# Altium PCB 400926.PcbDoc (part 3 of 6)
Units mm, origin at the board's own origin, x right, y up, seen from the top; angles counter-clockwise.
Board outline 148.5 x 63.5 mm, 4 copper layers (Top Layer, Mid-Layer 1, Mid-Layer 2, Bottom Layer), stack 1.514 mm thick; 311 components, 281 nets, 1495 pads, 2232 vias.
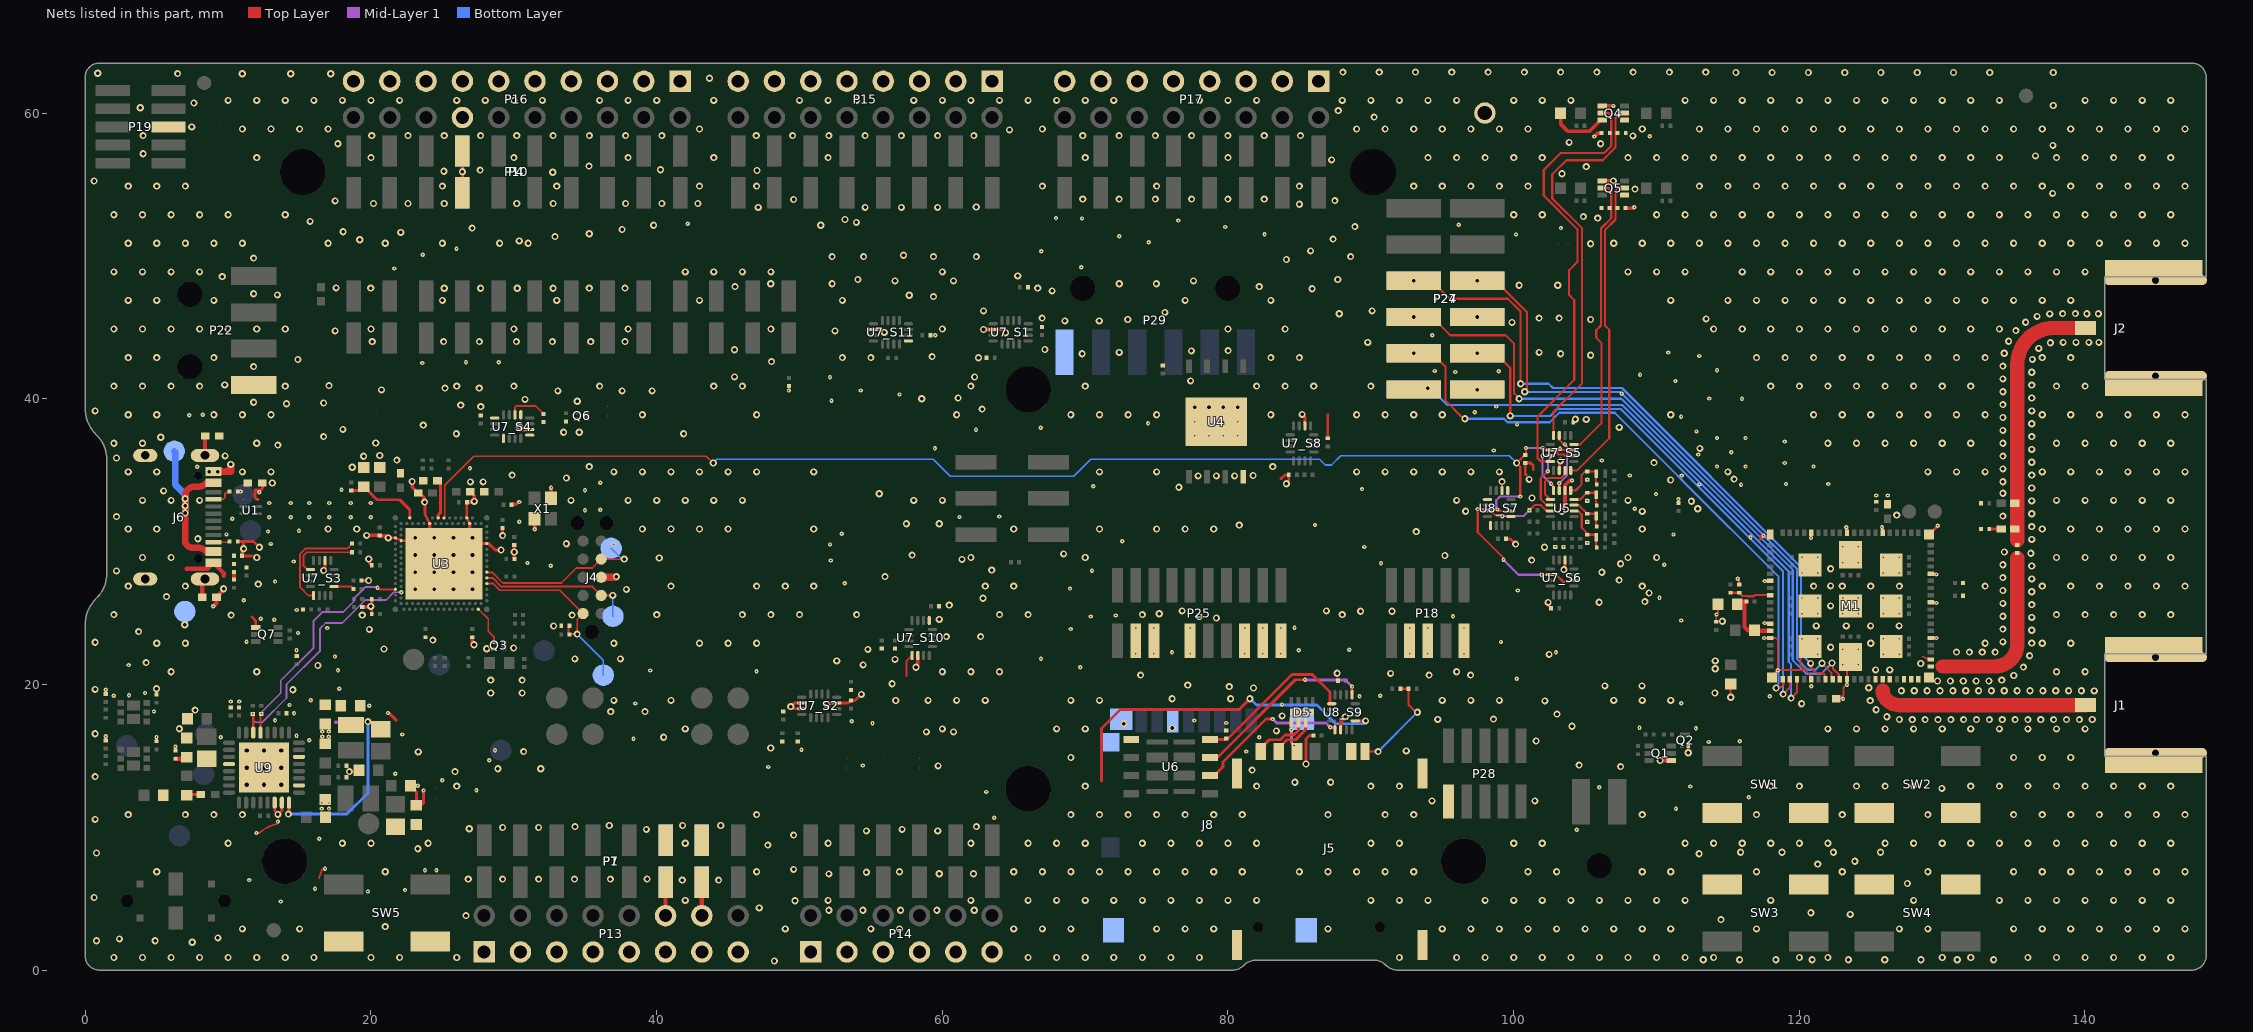
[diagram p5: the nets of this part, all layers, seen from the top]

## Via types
v1: diameter 0.5, hole 0.25, Top Layer to Bottom Layer, tented both sides, 1704 vias
v2: diameter 0.3, hole 0.1, Top Layer to Mid-Layer 1, tented top, 426 vias
v3: diameter 0.3, hole 0.1, Top Layer to Mid-Layer 1, tented both sides, 93 vias
v4: diameter 0.61, hole 0.305, Top Layer to Bottom Layer, tented both sides, 9 vias

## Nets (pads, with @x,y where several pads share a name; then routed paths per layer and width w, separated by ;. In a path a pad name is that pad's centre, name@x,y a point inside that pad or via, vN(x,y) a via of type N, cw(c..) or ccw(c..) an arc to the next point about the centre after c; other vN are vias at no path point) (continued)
GND: C1.2 C2.2 C3.2 C4.2 C5.2 C6.2 C7.2 C8.1 C9.1 C10.2 C11.1 C19.1 C24.1 C25.1 C26.2 C27.1 C28.2 C29.1 C30.2 C31.1 C32.1 C33.1 C34.2 C35.1 C36.1 C37.2 C38.2 C39.2 C40.1 C41.1 C42.1 C43.1 C44.2 C45.1 C46.1 C47.1 C48.2 C49.1 C50.1 C51.1 C52_S1.2 C52_S2.2 C52_S3.2 C52_S4.2 C52_S5.2 C52_S6.2 C52_S8.2 C52_S10.2 C52_S11.2 C53_S7.2 C53_S9.2 C54.1 C55.1 C56.1 C57.1 C58.1 C59.1 C60.1 C61.2 C62.2 C63.2 C64.1 C65.1 C66.1 C67.1 C68.1 C69.1 C70.1 C71.1 C72.1 D5.9 J1.2 J2.2 J4.3 J5.0 J5.C5 J6.A1 J6.A12 J8.0 J8.6 J8.9 M1.1 M1.7 M1.13 M1.15 M1.20 M1.25 M1.30 M1.34 M1.36 M1.38 M1.39 M1.40 M1.41 M1.43 M1.46 M1.51 M1.55 M1.60 M1.66 M1.71 M1.76 M1.105 M1.106 M1.107 M1.108 M1.109 M1.110 M1.111 M1.112 M1.113 P1.6 P1.7 P4.7 P7.6 P7.7 P10.7 P13.1 P13.3 P13.5 P13.7 P13.9 P13.11 P13.12 P13.13 P13.14 P13.15 P14.1 P14.3 P14.5 P14.7 P14.9 P14.11 P15.1 P15.3 P15.5 P15.7 P15.9 P15.11 P15.13 P15.15 P16.1 P16.3 P16.5 P16.7 P16.9 P16.11 P16.13 P16.14 P16.15 P16.17 P16.19 P17.1 P17.3 P17.5 P17.7 P17.9 P17.11 P17.13 P17.15 P18.3 P18.5 P18.9 P19.5 P22.4 P24.8 P24.12 P25.3 P25.5 P25.9 P25.15 P25.17 P25.19 P27.8 P27.12 P28.1 P29.1 Q1.1 Q2.2 Q3.2 Q4.1 Q4.4 Q5.1 Q5.4 Q6.2 Q7.1 R3.1 R7.1 R13.2 R14.1 R17.2 R18.1 R24.1 R31.2 R32.1 R36.2 R37.2 R38.1 R43.1 R44.1 R45.1 R46.1 R47.1 R59.1 R65.1 R67.2 R68.1 R70.1 R71.1 R72.2 R73.1 R74.1 R76.2 R78.1 R80.2 R81.2 R85.2 R86.2 SB19.1 SW1.1 SW2.1 SW3.1 SW4.1 SW5.1 TP18.1 TP24.1 U1.5 U1.8 U3.104 U3.A25 U3.B12 U3.B26 U3.G1 U3.H2 U3.J31 U4.4 U4.9 U5.6 U6.1 U7_S1.6 U7_S2.6 U7_S2.7 U7_S2.15 U7_S3.6 U7_S4.6 U7_S5.6 U7_S6.6 U7_S8.6 U7_S10.6 U7_S11.6 U8_S7.6 U8_S9.6 U9.2 U9.6 U9.30 U9.31 U9.33 X1.2 X1.4 | length 105
  Top Layer w0.125: v2(12,9.599) 12.14,9.599 ccw(c12.14,9.724) 12.221,9.629 cw(c13.97,7.62) 13.4,10.222 ccw(c13.373,10.344) 13.497,10.333 ccw(c12.7,10.399) v2(13.5,10.399) ; 16.4,6.399 16.4,6.503 cw(c16.525,6.502) 16.41,6.552 ccw(c13.97,7.62) 16.555,6.975 cw(c16.676,6.944) 16.618,7.055 cw(c16.8,6.699) v2(16.8,7.099) ; C1.2@114.19,24.384 114.204,24.398 114.204,24.882 v3(114.219,24.897) 114.219,24.944 114.325,25.05 C7.2@114.325,25.599 ; C3.2@115.2,19.949 115.2,19.111 v1(115.212,19.099) ; v3(115.705,27.399) 115.705,27.351 115.8,27.256 C10.2@115.8,26.984 ; 117.2,30.099 117.3,30.199 117.3,30.399 v3(117.5,30.399) 117.875,30.399 M1.1@117.975,30.499 ; v2(117.55,23.249) M1.15@117.975,23.249 118.35,23.249 118.5,23.099 v3(118.5,20.999) 120.43,20.999 ; M1.107@120.75,22.649 120.65,22.649 120.1,22.099 120.1,21.329 120.43,20.999 ; M1.25@120.85,20.374 120.763,20.461 120.763,20.667 120.43,20.999 ; C6.2@122.85,18.999 123.114,19.263 123.114,19.813 123.336,20.035 123.336,20.36 M1.30@123.35,20.374 123.35,21.674 M1.108@123.6,21.924 ; 128.642,21.944 128.744,21.944 128.87,21.817 129.157,21.817 M1.43@129.225,21.749
  Top Layer w0.15: P4.7@26.416,54.415 P4.7@26.416,57.345 ; U8_S7.6@99.2,33.574 v1(99.2,34.199)
  Top Layer w0.165: U3.A25@26.725,31.658 U3.B26@26.925,31.258
  Top Layer w0.187: v1(21.225,30.258) U3.G1@21.725,30.258 U3.G1@21.725,30.258 cw(c21.634,30.094) U3.G1@21.766,30.227 ; U3.G1@21.766,30.227 21.775,30.219 ccw(c21.907,30.351) 21.907,30.164 21.957,30.164 cw(c21.956,29.977) U3.H2@22.125,30.058 U3.104@22.825,30.058 ; v1@23.8,32.862 23.8,31.971 23.8,31.928 23.819,31.889 U3.B12@24.125,31.258
  Top Layer w0.2: R80.2@1.45,16.084 v2(1.448,16.367) ; R76.2@1.45,19.334 v2(1.448,19.617) ; R81.2@5,16.019 v2@5,16.302 ; v2(6.325,15.649) v2(6.325,15.649) C67.1@6.327,15.366 ; C54.1@7.127,12.246 7.18,12.299 C64.1@8.1,12.299 ; R70.1@10.685,29.999 11.1,29.999 ; R71.1@10.685,33.499 R71.1@10.714,33.528 ; v1@10.985,29.499 C8.1@10.985,28.999 11.65,28.999 ; v1(11.1,29.499) 11.1,29.999 ; 11.68,24.719 11.95,24.449 11.95,24.074 Q7.1@11.95,23.999 ; U1.8@12.1,32.949 cw(c12.1,33.149) 11.9,33.149 11.9,33.599 12.2,33.599 ccw(c12.2,33.824) 12.425,33.824 12.425,34.074 ccw(c12.4,34.074) C9.1@12.4,34.099 ; v1(12.2,29.599) 11.8,29.999 11.1,29.999 ; U9.30@13.275,11.724 13.275,11.166 13.5,10.941 v1(13.5,10.899) 13.775,11.174 U9.31@13.775,11.724 ; v1(16.7,27.974) 16.8,28.074 U7_S3.6@16.8,28.674 ; R24.1@19.36,27.274 v1(19.85,27.274) ; R65.1@19.4,25.414 v1@19.956,25.414 ; v1(20,25.458) 20.065,25.393 R31.2@20.065,24.924 ; v1@20.065,25.523 C26.2@20.065,25.958 ; v2(21.2,17.999) 21.219,17.98 21.294,17.98 21.787,17.486 ; C69.1@22.777,12.896 22.777,12.871 23.052,12.596 23.076,12.596 23.194,12.479 C70.1@23.194,11.548 23.245,11.599 23.583,11.599 23.7,11.716 v2@23.7,12.599 ; U3.A25@26.725,31.658 C39.2@26.725,32.754 ; v1@28.075,22.499 v1(28.125,22.499) Q3.2@28.625,22.499 ; U7_S2.7@50.175,18.299 49.55,18.299 v1(49.4,18.449) 49.65,18.699 U7_S2.6@50.175,18.699 ; v1(51.925,18.599) 52.025,18.699 U7_S2.15@52.625,18.699 53.44,18.699 C52_S2.2@53.6,18.859 ; C52_S2.2@53.625,18.884 53.91,18.884 54.15,19.124 ; U7_S11.6@55.193,44.849 55.748,44.849 v1(55.948,44.649) ; 83.725,34.399 83.996,34.67 C52_S8.2@84.268,34.67 84.268,34.217 v1(84.1,34.049) ; v1(85.2,38.899) 85.4,38.699 U7_S8.6@85.4,38.099 ; v1(85.475,14.429) 85.475,16.174 85.725,16.424 C48.2@85.99,16.424 ; 87,38.882 87.003,38.88 R38.1@87.003,37.23 ; C53_S7.2@99.482,30.191 99.783,30.191 v1(100.15,29.824) ; 100.9,34.649 100.825,34.724 R47.1@100.825,35.489 101.236,35.489 101.388,35.337 101.388,35.037 ; v1(102.429,25.743) 102.486,25.685 102.486,25.5 102.638,25.348 C52_S6.2@102.638,25.333 ; U7_S5.6@103.21,34.983 103.21,35.574 v1(103.285,35.649) ; v1(103.535,28.042) 103.61,28.117 U7_S6.6@103.61,28.708 ; R46.1@106.16,53.349 R46.1@106.195,53.314 ; v1(112.24,15.22) Q2.2@112.24,15.749 ; v3(117.588,27.236) 117.595,27.242 117.968,27.242 M1.7@117.975,27.249 ; v3(117.6,24.299) 117.619,24.28 117.944,24.28 M1.13@117.975,24.249 ; M1.20@118.1,20.499 118.35,20.749 118.35,20.832 118.5,20.982 v3(118.5,20.999) ; v3(120.838,30.248) 120.844,30.254 120.844,30.618 M1.76@120.85,30.624 ; v3(123.3,30.999) 123.35,30.949 M1.71@123.35,30.624 ; v3(125.8,30.999) 125.85,30.949 M1.66@125.85,30.624 ; M1.60@129.1,30.499 v3(129.7,31.099) ; M1.46@129.225,23.249 v3(129.605,23.248) ; M1.51@129.225,25.749 129.256,25.718 129.581,25.718 v3(129.6,25.699) ; M1.55@129.225,27.749 129.55,27.749 v3(129.6,27.699)
  Top Layer w0.225: v1(19.864,28.778) 19.917,28.725 19.917,28.496 20.065,28.348 C25.1@20.065,28.333 ; U3.104@24.125,29.858 U3.B12@24.125,31.258 ; U3.B26@26.925,31.258 26.925,29.858 U3.J31@28.125,29.858 28.275,29.858 28.725,29.408 v1(29.125,29.408) ; v1@29.225,30.425 C33.1@29.225,30.948 ; C34.2@29.86,32.574 29.86,32.588 29.882,32.611 30.176,32.611 30.331,32.765 v2(30.405,32.765) ; C30.2@30.05,29.748 v1(30.05,29.27) 30.05,28.793 C32.1@30.06,28.783
  Top Layer w0.25: C51.1@10.425,27.334 C50.1@10.425,27.864 ; v1(19.708,30.433) 19.713,30.428 20.6,30.428 C24.1@20.6,30.433 ; C24.1@20.625,30.423 20.65,30.413 20.995,30.413 cw(c20.994,30.163) v1(21.225,30.258) ; v1(22.9,34.208) 22.9,33.813 23.15,33.563 23.15,33.513 23.275,33.388 C40.1@23.325,33.388 ; C40.1@23.325,33.483 23.75,33.058 v1@23.75,32.908 ; C39.2@26.725,32.754 v1@27.196,32.754 ; C28.2@26.975,33.483 27.25,33.208 v1(27.25,32.808) ; C31.1@27.1,23.298 27.1,22.908 v1(27.229,22.778) ; v2(31.475,30.859) X1.4@31.475,31.587 ; X1.2@32.625,33.037 v2(32.625,33.766) ; R45.1@107.848,53.349 108.38,53.349 108.438,53.406 v2(108.465,53.406) ; v1(110.265,14.674) Q1.1@111.04,14.674
  Top Layer w0.254: v1(30.4,38.049) 30.6,37.849 U7_S4.6@31.125,37.849 ; v1(58.175,21.199) 58.3,21.324 U7_S10.6@58.3,22.024 ; v1(62.9,44.847) 62.902,44.849 U7_S1.6@63.575,44.849 64.225,44.849 64.475,44.599 v1(64.45,44.624) ; U8_S9.6@87.9,16.824 87.9,17.399 v1(88.225,17.724) ; 103.4,32.474 103.61,32.684 U5.6@103.61,33.574 103.612,33.576 103.612,33.936 103.95,34.274 v2(104.1,34.274) ; R59.1@103.488,29.618 103.496,29.626 v2(103.511,29.626) ; v2(105.657,58.354) 105.88,58.576 106.163,58.576 106.171,58.584 R44.1@106.171,58.599 ; Q5.4@106.25,55.249 v1(107,55.249) ; Q4.4@106.25,60.499 v2(107,60.499)
  Top Layer w0.3: 7.1,28.099 8.58,28.099 J6.A12@8.985,28.504 9.7,27.789 9.7,27.599 ; v2(8.97,25.462) 9.2,25.691 C63.2@9.2,26.099 9.7,26.599 v1(9.7,26.699) ; P13.12@40.64,3.81 P1.6@40.64,6.155 ; P13.14@43.18,3.81 P1.7@43.18,6.155
  Top Layer w0.5: J6.A1@8.985,34.904 9.295,34.904 v1(9.3,34.899) 10.2,34.899 v1(10.2,35.399) ; J4.3@36.135,27.499 v1@37.15,27.499
  Mid-Layer 1 w0.2: v3@120.838,30.221 v3(120.838,30.248)
  Mid-Layer 1 w0.25: 17.568,17.342 17.575,17.349
  Bottom Layer w0.15: P10.7@26.416,54.415 P10.7@26.416,57.345
  other v1: 48.26,0.635 113.292,0.723 115.832,0.723 118.372,0.723 120.912,0.723 123.452,0.723 125.992,0.723 128.532,0.723 131.072,0.723 133.612,0.723 2.018,0.882 4.018,0.882 6.018,0.882 8.018,0.882 10.018,0.882 12.018,0.882 14.018,0.882 16.018,0.882 20.018,0.882 22.018,0.882 26.018,0.882 66.018,0.882 68.018,0.882 70.018,0.882 72.018,0.882 74.018,0.882 76.018,0.882 78.018,0.882 92.018,0.882 96.018,0.882 98.018,0.882 100.018,0.882 102.018,0.882 104.018,0.882 106.018,0.882 108.018,0.882 110.018,0.882 112.018,0.882 114.018,0.882 120.018,0.882 122.018,0.882 130.018,0.882 132.018,0.882 136.018,0.882 138.018,0.882 140.018,0.882 142.018,0.882 144.018,0.882 146.018,0.882 7.5,1.949 0.8,2.049 4.9,2.049 2.4,2.184 9.3,2.249 11.018,2.882 15.018,2.882 49.018,2.882 55.018,2.882 57.018,2.882 65.018,2.882 67.018,2.882 69.018,2.882 75.018,2.882 77.018,2.882 79.018,2.882 87.018,2.882 95.018,2.882 97.018,2.882 99.018,2.882 101.018,2.882 103.018,2.882 105.018,2.882 107.018,2.882 109.018,2.882 111.018,2.882 117.018,2.882 127.018,2.882 129.018,2.882 135.018,2.882 137.018,2.882 139.018,2.882 141.018,2.882 143.018,2.882 145.018,2.882 147.018,2.882 21.012,3.048 114.529,3.53 26.67,3.81 123.575,3.899 120.828,4.012 52.07,4.191 54.458,4.191 57.099,4.191 59.639,4.191 62.255,4.191 47.2,4.349 49.7,4.849 42.018,4.882 52.018,4.882 62.018,4.882 66.018,4.882 68.018,4.882 70.018,4.882 72.018,4.882 74.018,4.882 76.018,4.882 78.018,4.882 80.018,4.882 82.018,4.882 90.018,4.882 92.018,4.882 94.018,4.882 98.018,4.882 100.018,4.882 102.018,4.882 104.018,4.882 106.018,4.882 108.018,4.882 110.018,4.882 112.018,4.882 118.018,4.882 128.018,4.882 134.018,4.882 136.018,4.882 138.018,4.882 140.018,4.882 142.018,4.882 144.018,4.882 146.018,4.882 0.635,5.08 127.583,6.062 41.808,6.299 44.348,6.299 26.822,6.374 29.235,6.374 31.75,6.374 34.265,6.374 36.779,6.374 39.345,6.375 52.07,6.731 59.8,6.749 62.2,6.749 54.7,6.849 5.018,6.882 21.018,6.882 47.018,6.882 57.018,6.882 65.018,6.882 67.018,6.882 69.018,6.882 71.018,6.882 73.018,6.882 75.018,6.882 77.018,6.882 79.018,6.882 81.018,6.882 85.018,6.882 87.018,6.882 89.018,6.882 91.018,6.882 93.018,6.882 101.018,6.882 103.018,6.882 109.018,6.882 111.018,6.882 117.018,6.882 123.018,6.882 129.018,6.882 135.018,6.882 137.018,6.882 139.018,6.882 141.018,6.882 143.018,6.882 145.018,6.882 147.018,6.882 49.6,7.049 121.3,7.424 123.9,7.624 113,8.149 0.8,8.199 115.9,8.249 118.8,8.249 122.4,8.249 125.7,8.249 23.3,8.499 47.8,8.749 10.018,8.882 18.018,8.882 20.018,8.882 24.018,8.882 42.018,8.882 52.018,8.882 62.018,8.882 66.018,8.882 68.018,8.882 70.018,8.882 74.018,8.882 76.018,8.882 78.018,8.882 80.018,8.882 82.018,8.882 90.018,8.882 92.018,8.882 100.018,8.882 102.018,8.882 112.018,8.882 114.018,8.882 116.018,8.882 118.018,8.882 120.018,8.882 122.018,8.882 126.018,8.882 128.018,8.882 130.018,8.882 132.018,8.882 134.018,8.882 136.018,8.882 138.018,8.882 140.018,8.882 142.018,8.882 144.018,8.882 146.018,8.882 49.6,9.449 54.7,9.749 59.7,9.749 39.3,9.849 57.2,9.849 26.9,9.899 29.235,9.982 31.75,9.982 34.3,10.049 62.4,10.049 36.7,10.124 41.834,10.124 44.501,10.124 0.7,10.549 3.018,10.882 7.018,10.882 9.018,10.882 11.018,10.882 47.018,10.882 69.018,10.882 71.018,10.882 73.018,10.882 75.018,10.882 77.018,10.882 79.018,10.882 81.018,10.882 87.018,10.882 91.018,10.882 93.018,10.882 109.018,10.882 117.018,10.882 123.018,10.882 129.018,10.882 135.018,10.882 137.018,10.882 139.018,10.882 141.018,10.882 143.018,10.882 145.018,10.882 147.018,10.882 94.3,11.849 101.5,11.849 129.997,12.724 26.018,12.882 70.018,12.882 82.018,12.882 90.018,12.882 92.018,12.882 118.018,12.882 120.018,12.882 124.018,12.882 126.018,12.882 128.018,12.882 132.018,12.882 134.018,12.882 136.018,12.882 138.018,12.882 140.018,12.882 142.018,12.882 144.018,12.882 146.018,12.882 84.7,13.149 87.2,13.149 0.7,13.549 18.5,13.899 25.9,13.899 81.7,13.999 28.9,14.099 31.9,14.099 107.5,14.249 59.725,14.299 104.6,14.349 69.018,14.882 135.018,14.882 137.018,14.882 139.018,14.882 23.325,15.274 30.7,15.299 92.5,15.349 48,15.549 101.591,16.04 40.5,16.299 0.7,16.549 58.9,16.674 60.8,16.674 83.4,16.749 6.6,16.899 42.018,16.882 60.018,16.882 68.018,16.882 70.018,16.882 122.018,16.882 124.018,16.882 126.018,16.882 128.018,16.882 130.018,16.882 132.018,16.882 134.018,16.882 136.018,16.882 138.018,16.882 140.018,16.882 76.1,16.949 104.1,17.074 72.725,17.249 94.7,17.549 127.021,17.543 127.921,17.54 128.821,17.54 129.721,17.54 130.621,17.54 131.521,17.54 132.421,17.54 133.321,17.54 134.221,17.54 135.121,17.54 136.021,17.54 136.921,17.54 137.821,17.54 138.721,17.54 139.621,17.54 140.521,17.542 98.602,17.57 126.141,17.733 83.8,17.799 103.05,17.924 36.8,18.099 39.2,18.099 7.7,18.199 125.391,18.23 120.175,18.649 102.2,18.849 56.75,18.874 124.979,18.866 37.018,18.882 41.018,18.882 59.018,18.882 61.018,18.882 63.018,18.882 69.018,18.882 71.018,18.882 95.018,18.882 97.018,18.882 99.018,18.882 107.018,18.882 109.018,18.882 111.018,18.882 76.1,18.999 80.2,18.999 54.35,19.299 28.4,19.399 30.6,19.399 114.1,19.399 140.663,19.542 127.163,19.558 128.063,19.558 128.963,19.558 129.863,19.558 130.763,19.558 131.663,19.558 132.563,19.558 133.463,19.558 134.363,19.558 135.263,19.558 136.163,19.558 137.063,19.558 137.963,19.558 138.863,19.558 139.763,19.558 14.55,19.625 0.7,19.649 5,19.699 81.8,19.749 124.879,19.766 80.1,19.849 106.4,19.899 109,19.899 77.2,19.949 56.5,20.049 129.689,20.24 130.589,20.24 131.489,20.24 132.389,20.24 133.289,20.24 28.4,20.299 30.6,20.299 134.187,20.296 135.027,20.621 73.9,20.649 94.1,20.649 97,20.649 87.65,20.784 91.4,20.774 6.018,20.882 12.018,20.882 60.018,20.882 62.018,20.882 64.018,20.882 96.018,20.882 138.018,20.882 140.018,20.882 125.35,21.014 126.35,21.014 114.125,21.099 135.702,21.215 16.3,21.325 54.468,21.361 128.513,21.464 4.275,21.525 52.625,21.649 114.125,21.649 56.7,21.749 34.29,21.789 37.482,21.789 136.14,22.002 102.5,22.099 131.02,22.258 131.92,22.258 132.82,22.258 133.72,22.261 54.8,22.449 20.929,22.478 30,22.549 122.2,22.599 5.018,22.882 7.018,22.882 37.018,22.882 43.018,22.882 45.018,22.882 47.018,22.882 125.018,22.882 133.018,22.882 136.289,22.89 137.018,22.882 139.018,22.882 0.7,22.949 134.271,22.973 24.35,23.099 60.3,23.349 62.7,23.349 3.75,23.7 136.289,23.79 19.9,23.849 134.271,23.873 32.803,24.09 121.2,24.099 123.3,24.099 125,24.099 127,24.099 6.975,24.175 114.625,24.424 59.8,24.549 79.2,24.649 136.289,24.69 78,24.749 134.271,24.773 10.225,24.85 19.4,24.849 34.1,24.849 2.018,24.882 40.018,24.882 46.018,24.882 48.018,24.882 50.018,24.882 54.018,24.882 64.018,24.882 66.018,24.882 74.018,24.882 88.018,24.882 138.018,24.882 140.018,24.882 142.018,24.882 144.018,24.882 146.018,24.882 75.2,24.949 89.3,25.124 91.5,25.124 76.8,25.149 86.9,25.149 122.2,25.499 60.5,25.549 136.289,25.59 134.271,25.673 106,25.749 109.2,25.799 62.865,26.034 5.7,26.149 109.5,26.399 136.289,26.49 134.271,26.573 37.9,26.649 23.125,26.658 24.458,26.658 25.792,26.658 27.125,26.658 3.018,26.882 7.018,26.882 41.018,26.882 47.018,26.882 49.018,26.882 51.018,26.882 63.018,26.882 65.018,26.882 109.018,26.882 121.018,26.882 123.018,26.882 125.018,26.882 127.018,26.882 133.018,26.882 137.018,26.882 139.018,26.882 141.018,26.882 143.018,26.882 145.018,26.882 147.018,26.882 122.2,26.899 12.125,27.025 107.4,27.299 136.289,27.39 134.271,27.473 37.2,27.549 56,27.549 23.125,27.858 24.458,27.858 25.792,27.858 27.125,27.858 106.193,27.856 2.2,27.949 63.474,28 122.2,28.099 136.289,28.29 134.271,28.373 107.5,28.449 101.275,28.699 61.392,28.752 40.2,28.849 4.018,28.882 6.018,28.882 12.018,28.882 62.018,28.882 70.018,28.882 108.018,28.882 110.018,28.882 138.018,28.882 140.018,28.882 142.018,28.882 144.018,28.882 146.018,28.882 95.2,29.024 23.125,29.058 24.458,29.058 25.792,29.058 27.125,29.058 57.9,29.049 68.504,29.133 136.222,29.187 134.371,29.268 102.175,29.599 33.7,29.849 136.289,30.15 7.9,30.199 23.125,30.258 24.458,30.258 25.792,30.258 27.125,30.258 29.23,30.42 93.2,30.699 3.018,30.882 5.018,30.882 17.018,30.882 19.018,30.882 39.018,30.882 41.018,30.882 43.018,30.882 45.018,30.882 51.018,30.882 65.018,30.882 71.018,30.882 75.018,30.882 77.018,30.882 79.018,30.882 109.018,30.882 137.018,30.882 139.018,30.882 141.018,30.882 143.018,30.882 145.018,30.882 147.018,30.882 136.289,31.05 80.8,31.149 57.5,31.249 59.8,31.249 2.2,31.749 134.271,31.785 126.838,31.853 136.289,31.95 109.021,32.108 96.65,32.124 103.4,32.124 112.9,32.299 23.775,32.758 112.46,32.821 136.289,32.85 4.018,32.882 6.018,32.882 8.018,32.882 34.018,32.882 38.018,32.882 40.018,32.882 42.018,32.882 44.018,32.882 46.018,32.882 58.018,32.882 60.018,32.882 96.018,32.882 108.018,32.882 138.018,32.882 140.018,32.882 142.018,32.882 144.018,32.882 146.018,32.882 101.3,33.049 55.6,33.349 134.271,33.385 5.5,33.549 136.289,33.75 76.575,33.799 13.1,34.099 26.976,34.174 27.862,34.174 134.271,34.185 111,34.313 101.1,34.349 115.45,34.374 33.7,34.449 77.925,34.599 79.2,34.599 80.475,34.599 81.775,34.624 29.9,34.649 136.289,34.65 3.018,34.882 5.018,34.882 11.018,34.882 13.018,34.882 37.018,34.882 39.018,34.882 41.018,34.882 43.018,34.882 45.018,34.882 47.018,34.882 51.018,34.882 71.018,34.882 75.018,34.882 89.018,34.882 91.018,34.882 93.018,34.882 95.018,34.882 97.018,34.882 99.018,34.882 115.018,34.882 129.018,34.882 131.018,34.882 133.018,34.882 137.018,34.882 139.018,34.882 141.018,34.882 143.018,34.882 145.018,34.882 147.018,34.882 8.7,34.899 134.271,35.085 18.7,35.199 35.3,35.249 83.15,35.249 109.838,35.523 136.289,35.55 21.825,35.708 2.2,35.849 19.5,35.974 9.8,35.999 134.271,35.985 20.625,36.024 136.289,36.45 113.05,36.524 13.5,36.749 2.018,36.882 4.018,36.882 12.018,36.882 122.018,36.882 124.018,36.882 126.018,36.882 128.018,36.882 130.018,36.882 132.018,36.882 134.271,36.885 138.018,36.882 140.018,36.882 142.018,36.882 144.018,36.882 146.018,36.882 20.35,36.899 5.3,37.299 16.7,37.349 136.289,37.35 26,37.549 41.9,37.549 33.5,37.649 34.6,37.649 134.271,37.785 18.05,37.849 107.406,37.992 23.675,38.149 136.289,38.25 104.333,38.566 105.1,38.549 134.271,38.685 3.018,38.882 5.018,38.882 9.018,38.882 11.018,38.882 13.018,38.882 39.018,38.882 47.018,38.882 61.018,38.882 69.018,38.882 71.018,38.882 73.018,38.882 75.018,38.882 83.018,38.882 89.018,38.882 91.018,38.882 93.018,38.882 95.018,38.882 111.018,38.882 121.018,38.882 123.018,38.882 125.018,38.882 127.018,38.882 129.018,38.882 131.018,38.882 133.018,38.882 137.018,38.882 139.018,38.882 141.018,38.882 143.018,38.882 145.018,38.882 147.018,38.882 0.7,39.149 136.289,39.15 62.8,39.274 77.687,39.399 78.687,39.399 79.687,39.399 80.687,39.399 27.7,39.449 26.3,39.549 134.271,39.585 14.1,39.649 16.7,39.699 11.8,39.749 34.457,39.823 30.8,39.949 58.575,39.999 61.125,40.049 136.289,40.05 134.271,40.485 33.1,40.549 37.6,40.549 39.7,40.549 20.75,40.624 97.472,40.64 25.2,40.749 27.6,40.749 2.018,40.882 4.018,40.882 6.018,40.882 8.018,40.882 14.018,40.882 26.018,40.882 30.018,40.882 36.018,40.882 44.018,40.882 46.018,40.882 62.018,40.882 70.018,40.882 82.018,40.882 84.018,40.882 86.018,40.882 90.018,40.882 118.018,40.882 120.018,40.882 122.018,40.882 124.018,40.882 126.018,40.882 128.018,40.882 130.018,40.882 132.018,40.882 138.018,40.882 140.018,40.882 17.075,40.924 136.289,40.95 9.779,40.968 77.4,41.249 134.271,41.385 45.466,41.528 62.275,41.524 136.289,41.85 11.8,42.249 134.271,42.285 48.057,42.595 14.9,42.749 136.327,42.75 3.018,42.882 5.018,42.882 9.018,42.882 53.018,42.882 55.018,42.882 62.55,42.874 83.018,42.882 85.018,42.882 117.018,42.882 119.018,42.882 121.018,42.882 123.018,42.882 125.018,42.882 127.018,42.882 129.018,42.882 131.018,42.882 133.018,42.882 137.018,42.882 139.018,42.882 59.3,42.949 105.4,43.049 69.8,43.149 103.3,43.149 134.365,43.18 72.4,43.249 101.8,43.249 77.45,43.349 80.025,43.374 45.466,43.434 67.2,43.449 136.777,43.529 137.587,43.921 89.8,43.949 138.487,43.94 139.387,43.94 140.287,43.942 140.99,43.942 20.1,43.999 25.1,43.999 27.61,43.999 30.201,43.999 32.715,43.999 35.4,43.999 37.8,43.999 134.667,44.028 17.5,44.749 52.5,44.749 135.18,44.768 2.018,44.882 4.018,44.882 6.018,44.882 8.018,44.882 10.018,44.882 12.018,44.882 14.018,44.882 20.018,44.882 30.018,44.882 38.018,44.882 48.018,44.882 60.018,44.882 80.018,44.882 84.018,44.882 114.018,44.882 116.018,44.882 118.018,44.882 120.018,44.882 122.018,44.882 124.018,44.882 126.018,44.882 128.018,44.882 130.018,44.882 132.018,44.882 134.018,44.882 99.9,45.349 135.859,45.358 68.6,45.449 71,45.449 73,45.549 105.4,45.549 113.485,45.594 67,45.649 101.8,45.649 103.2,45.649 97.472,45.72 136.664,45.761 87.8,45.949 137.546,45.938 140.148,45.949 140.951,45.949 138.446,45.958 139.346,45.958 75.6,46.049 62.9,46.149 90.1,46.149 3.018,46.882 5.018,46.882 9.018,46.882 25.018,46.882 33.018,46.882 43.018,46.882 53.018,46.882 77.018,46.882 83.018,46.882 111.018,46.882 115.018,46.882 117.018,46.882 119.018,46.882 121.018,46.882 123.018,46.882 125.018,46.882 127.018,46.882 129.018,46.882 131.018,46.882 133.018,46.882 135.018,46.882 137.018,46.882 139.018,46.882 59.4,47.149 57.7,47.249 13.462,47.268 11.8,47.349 67.7,47.549 85.9,47.699 25.146,47.73 27.686,47.73 30.251,47.73 32.766,47.73 17.572,47.756 20,47.749 35.3,47.749 37.8,47.749 66.7,47.749 45.5,47.849 82.2,47.849 100.4,47.949 103.1,47.949 48,48.049 52.3,48.049 72.4,48.049 75,48.049 56.7,48.249 60.8,48.249 77.6,48.249 54.1,48.349 87.7,48.349 9.6,48.549 65.3,48.599 2.018,48.882 4.018,48.882 6.018,48.882 8.018,48.882 42.018,48.882 44.018,48.882 46.018,48.882 48.018,48.882 60.018,48.882 108.018,48.882 110.018,48.882 112.018,48.882 116.018,48.882 118.018,48.882 120.018,48.882 122.018,48.882 124.018,48.882 126.018,48.882 128.018,48.882 130.018,48.882 132.018,48.882 134.018,48.882 136.018,48.882 138.018,48.882 140.018,48.882 84.1,49.749 11.8,49.849 52.3,49.949 54.5,49.949 59.4,49.949 62.4,49.949 88.6,49.949 57.3,50.049 85.8,50.349 105.4,50.849 3.018,50.882 5.018,50.882 7.018,50.882 9.018,50.882 11.018,50.882 17.018,50.882 21.018,50.882 25.018,50.882 29.018,50.882 31.018,50.882 107.018,50.882 109.018,50.882 111.018,50.882 113.018,50.882 115.018,50.882 117.018,50.882 119.018,50.882 121.018,50.882 123.018,50.882 125.018,50.882 127.018,50.882 129.018,50.882 131.018,50.882 133.018,50.882 135.018,50.882 137.018,50.882 139.018,50.882 141.018,50.882 143.018,50.882 145.018,50.882 147.018,50.882 30.4,51.049 19.228,51.129 87.374,51.175 32.9,51.349 35.3,51.549 22.1,51.649 18.059,51.688 37.6,51.849 27.1,51.949 88.9,52.049 39.8,52.149 51.5,52.149 54,52.349 15.756,52.418 53.2,52.549 105.9,52.649 104.9,52.749 2.018,52.882 4.018,52.882 6.018,52.882 8.018,52.882 10.018,52.882 14.018,52.882 100.018,52.882 102.018,52.882 110.018,52.882 112.018,52.882 114.018,52.882 116.018,52.882 118.018,52.882 120.018,52.882 122.018,52.882 124.018,52.882 126.018,52.882 128.018,52.882 130.018,52.882 132.018,52.882 134.018,52.882 136.018,52.882 138.018,52.882 140.018,52.882 142.018,52.882 144.018,52.882 146.018,52.882 47.124,53.394 54.61,53.394 57.15,53.394 59.69,53.394 62.391,53.424 85.014,53.618 20.193,53.666 22.606,53.666 25.146,53.666 30.226,53.666 32.766,53.666 37.846,53.666 40.386,53.666 42.901,53.666 17.5,53.849 87.503,53.872 49.6,53.949 69.85,53.975 72.39,53.975 74.93,53.975 77.47,53.975 80.01,53.975 82.55,53.975 137.744,54.38 108.512,54.681 3.018,54.882 5.018,54.882 7.018,54.882 25.018,54.882 33.018,54.882 43.018,54.882 47.018,54.882 67.018,54.882 75.018,54.882 85.018,54.882 93.018,54.882 95.018,54.882 97.018,54.882 99.018,54.882 101.018,54.882 113.018,54.882 115.018,54.882 117.018,54.882 119.018,54.882 121.018,54.882 123.018,54.882 125.018,54.882 127.018,54.882 129.018,54.882 131.018,54.882 133.018,54.882 135.018,54.882 137.018,54.882 139.018,54.882 141.018,54.882 143.018,54.882 145.018,54.882 147.018,54.882 0.635,55.245 103.4,55.749 32.741,55.854 26.416,55.89 25.121,55.93 47.041,55.981 27.661,56.006 40.284,56.031 105.1,56.249 35.281,56.285 87.274,56.717 12.018,56.882 20.018,56.882 30.018,56.882 38.018,56.882 44.018,56.882 52.018,56.882 70.018,56.882 80.018,56.882 94.018,56.882 96.018,56.882 98.018,56.882 100.018,56.882 102.018,56.882 108.018,56.882 110.018,56.882 112.018,56.882 114.018,56.882 116.018,56.882 118.018,56.882 120.018,56.882 122.018,56.882 124.018,56.882 126.018,56.882 128.018,56.882 130.018,56.882 132.018,56.882 134.018,56.882 138.018,56.882 140.018,56.882 142.018,56.882 144.018,56.882 146.018,56.882 136.55,56.999 4.064,57.15 137.77,57.733 17.7,57.849 106.1,57.849 103.9,57.949 108.367,58.399 4.064,58.42 20.066,58.42 22.606,58.42 25.146,58.42 27.686,58.42 30.226,58.42 32.766,58.42 35.306,58.42 37.846,58.42 40.386,58.42 46.99,58.42 49.53,58.42 52.07,58.42 54.61,58.42 57.15,58.42 59.69,58.42 62.23,58.42 69.85,58.42 72.39,58.42 74.93,58.42 77.47,58.42 80.01,58.42 82.55,58.42 85.09,58.42 64.719,58.825 11.018,58.882 13.018,58.882 15.018,58.882 17.018,58.882 43.018,58.882 67.018,58.882 89.018,58.882 91.018,58.882 93.018,58.882 95.018,58.882 97.018,58.882 99.018,58.882 101.018,58.882 109.018,58.882 113.018,58.882 115.018,58.882 117.018,58.882 119.018,58.882 121.018,58.882 123.018,58.882 125.018,58.882 127.018,58.882 129.018,58.882 131.018,58.882 133.018,58.882 135.018,58.882 137.018,58.882 139.018,58.882 141.018,58.882 143.018,58.882 145.018,58.882 147.018,58.882 7.467,59.03 90.246,59.714 87.732,60.172 3.861,60.376 137.795,60.527 7.62,60.706 10.018,60.882 12.018,60.882 14.018,60.882 16.018,60.882 18.018,60.882 20.018,60.882 22.018,60.882 26.018,60.882 28.018,60.882 30.018,60.882 32.018,60.882 36.018,60.882 38.018,60.882 40.018,60.882 44.018,60.882 50.018,60.882 52.018,60.882 54.018,60.882 58.018,60.882 60.018,60.882 62.018,60.882 64.018,60.882 66.018,60.882 68.018,60.882 70.018,60.882 72.018,60.882 78.018,60.882 80.018,60.882 82.018,60.882 88.018,60.882 90.018,60.882 92.018,60.882 94.018,60.882 96.018,60.882 100.018,60.882 102.018,60.882 104.018,60.882 112.018,60.882 114.018,60.882 116.018,60.882 118.018,60.882 120.018,60.882 122.018,60.882 124.018,60.882 126.018,60.882 128.018,60.882 130.018,60.882 132.018,60.882 134.018,60.882 140.018,60.882 142.018,60.882 144.018,60.882 146.018,60.882 43.713,62.433 6.477,62.763 11,62.749 14.4,62.749 17.2,62.749 0.889,62.789 115.57,62.84 118.11,62.84 120.65,62.84 123.19,62.84 125.73,62.84 128.27,62.84 130.81,62.84 133.35,62.84 137.795,62.839 88.061,62.863 90.601,62.863 93.141,62.863 95.681,62.863 98.221,62.863 100.761,62.863 103.301,62.863 105.841,62.863 108.381,62.863 110.921,62.863 113.461,62.863
  other v2: 13.7,4.799 19.8,5.499 22.4,5.599 16.1,5.699 11.5,6.299 23.8,6.999 24.6,6.999 16.4,9.199 63.65,10.674 16.575,11.309 17.075,11.309 16.575,11.699 17.075,11.699 63.1,12.474 23.697,12.572 27.4,12.599 23.3,12.899 25,13.299 21.72,13.754 47.825,14.224 54.45,14.324 28.3,14.699 81.3,15.299 28.7,15.399 50.15,15.424 15.7,16.099 38.4,16.199 4.998,16.302 9.5,16.299 82.2,16.299 16.6,16.349 17.05,16.349 14.8,16.399 22.2,16.499 16.6,16.699 17.05,16.699 55.125,17.274 79.9,17.299 53.675,17.424 77.65,17.469 13.3,17.499 14.631,17.973 84.6,18.049 85.2,18.049 85.8,18.049 4.822,18.102 19.9,18.499 14.316,18.557 83.8,18.599 38.514,18.671 10.2,18.799 10.8,18.799 15.8,18.899 2,19.199 3.075,19.25 4.2,19.4 17.8,19.699 100.225,20.399 47,20.924 39.575,20.974 17.7,20.999 69.675,21.199 3.063,21.353 66.925,21.799 17.491,21.949 73.555,22.149 74.825,22.149 77.365,22.149 81.175,22.149 82.445,22.149 83.715,22.149 92.73,22.149 94,22.149 96.54,22.149 76.1,22.249 102.975,22.249 14.8,22.399 84.975,22.399 88.5,22.424 11.306,22.982 99.125,22.974 14.9,23.599 69,23.874 16.953,23.946 73.555,23.949 74.825,23.949 77.365,23.949 81.175,23.949 82.445,23.949 83.715,23.949 92.73,23.949 94,23.949 96.54,23.949 13.252,24.527 12.3,24.599 70.4,24.749 95.775,24.774 72.15,24.824 14.824,25.21 11.1,25.899 110.225,26.074 100.3,26.574 68.953,26.707 53.175,27.074 13.3,27.199 70.5,27.949 32.6,28.299 110.55,28.374 30.975,28.499 14.6,28.599 52.2,28.674 102.927,29.626 52.15,29.799 37,29.824 12.995,29.837 105.174,29.905 72.612,30.026 9.9,30.499 111.2,30.499 52.975,30.549 12.8,30.699 14.975,30.749 105.174,31.378 30.387,31.394 10.3,31.599 12.9,31.699 14.4,31.699 15.7,31.699 17.1,31.699 18.6,31.699 20,31.699 61.225,31.724 64,31.749 35,32.199 36.075,32.224 108.5,32.299 12.9,32.699 14.4,32.699 15.7,32.699 17.1,32.699 18.6,32.699 20,32.699 105.174,32.851 111.55,32.974 125.4,33.224 126.2,33.224 109.982,33.324 12.2,33.449 10.9,33.499 35,33.599 17.945,33.637 115.937,33.986 113,33.999 119.077,34.029 122.047,34.026 36.073,34.118 105.174,34.325 108.15,34.624 111.785,34.619 26.945,35.137 7.845,35.237 114.25,35.249 116.25,35.249 121,35.249 119,35.499 106.175,35.674 112.947,36.091 115.25,36.249 98.625,36.374 119,36.999 114.25,37.249 116.25,37.249 77.687,37.399 78.687,37.399 79.687,37.399 80.687,37.399 112.81,37.713 100.25,38.199 74.422,38.277 77.687,38.399 78.687,38.399 79.687,38.399 80.687,38.399 111.735,38.734 7.303,38.836 8.242,38.887 97.3,39.049 98.8,39.449 113.699,40.014 116,39.999 107.58,40.342 111.345,41.24 108.864,41.68 95.925,41.874 98.975,41.924 94.5,41.949 114.25,41.999 23.6,42.499 26.67,42.545 28.956,42.545 113,42.999 110.846,43.23 94.325,44.449 94.55,46.974 21.65,49.124 69.75,49.199 23.647,50.088 66.95,50.324 26.01,50.494 74.475,50.949 72.4,51.374 100.175,51.499 82.575,51.524 103.325,51.949 79.825,52.024 96.175,52.174 42.189,52.247 76.525,52.474 69.8,52.624 67.975,52.649 109.544,58.379
  other v3: 104.425,9.824 111.375,11.299 116.475,12.099 106,12.799 112.375,12.849 113.67,15.974 115.85,16.024 112.775,16.924 108.825,16.974 111.75,18.674 123.075,18.999 89.225,19.174 117.95,19.174 90.675,19.199 120.85,19.874 123.35,19.974 123.05,21.374 124.15,21.374 121.3,22.099 125.9,22.099 127,22.099 123.05,22.474 124.15,22.474 120.2,23.199 121.3,23.199 125.9,23.199 127,23.199 84.675,23.974 111.75,24.474 120.2,24.949 121.3,24.949 123.05,24.949 124.15,24.949 125.9,24.949 127,24.949 120.2,26.049 121.3,26.049 123.05,26.049 124.15,26.049 125.9,26.049 127,26.049 120.2,27.799 121.3,27.799 125.9,27.799 127,27.799 90.725,28.474 123.05,28.524 124.15,28.524 120.2,28.899 121.3,28.899 125.9,28.899 127,28.899 89.55,29.624 123.05,29.624 124.15,29.624 116.6,30.299 86.108,31.158 89.4,33.674 70.575,33.874 59.498,36.524 62.375,37.824 66.9,37.974 52.25,39.849 57.025,40.299 49.275,40.574 54.308,40.583 52.15,41.499 59.525,44.449
  other v4: 11.325,12.974 12.525,12.974 13.725,12.974 11.325,14.174 12.525,14.174 13.725,14.174 11.325,15.374 12.525,15.374 13.725,15.374
GPS_RF1: C12.2 M1.42 | length 12.1
  Top Layer w1: 130.05,21.249 133.68,21.249 ccw(c133.68,22.849) 135.28,22.849 135.28,28.849
GPS_RF2: C12.1 J2.1 L3.2 L4.1 | length 18.6
  Top Layer w1: 135.28,30.089 135.28,30.879 135.28,42.409 cw(c137.82,42.409) 137.82,44.949 139.85,44.949 J2.1@140.1,44.949
IMCU_LED: Q3.1 U3.AL29 | length 2.8
  Top Layer w0.125: U3.AL29@27.525,25.234 27.578,25.234 28.221,24.591 28.221,23.728 28.625,23.324 Q3.1@28.625,22.949
IMCU_RESET: C41.2 J4.10 R34.1 TP14.1 U3.AC31 | length 14.1
  Top Layer w0.125: U3.AC31@28.125,27.058 28.585,27.058 29.044,26.599 33.225,26.599 J4.10@34.865,24.959 34.45,24.544 v1(34.45,23.524) 33.86,23.524 33.835,23.499 C41.2@33.835,24.099
  Bottom Layer w0.125: v1(34.45,23.524) 36.283,21.691 TP14.1@36.283,20.649
IMCU_SCL: R84.1 U3.AF2 U9.14 | length 17.4
  Top Layer w0.15: v2(11.737,17.931) 11.775,17.893 U9.14@11.775,16.624
  Mid-Layer 1 w0.125: v2(11.737,17.931) 11.75,17.918 11.75,17.499 11.9,17.349 12.4,17.349 14.1,19.049 14.1,19.999 16.45,22.349 16.45,23.921 16.829,24.3 17.999,24.3 19.611,25.911 21.076,25.911 21.622,26.458 v2(22.125,26.458)
IMCU_SDA: R83.1 U3.AE1 U9.13 | length 16.3
  Top Layer w0.125: v2(20.475,26.774) 20.6,26.649 21.709,26.649 21.712,26.645 U3.AE1@21.725,26.658
  Top Layer w0.15: U9.13@12.275,16.624 12.275,17.871 12.335,17.931 v2(12.337,17.931)
  Mid-Layer 1 w0.125: v2(12.337,17.931) 12.351,17.946 12.351,18.05 13.7,19.399 13.7,20.274 16,22.574 16,24.461 16.6,25.061 18.054,25.061 18.832,25.84 18.832,26.033 19.61,26.812 20.39,26.812 20.428,26.774 v2(20.475,26.774)
IMCU_SWDCLK: J4.4 TP15.1 U3.W31 | length 11.9
  Top Layer w0.125: U3.W31@28.125,27.858 28.144,27.839 28.511,27.839 29.251,27.099 33.35,27.099 34.4,28.149 35.515,28.149 J4.4@36.135,28.769 v1(37.745,28.769)
  Bottom Layer w0.125: TP15.1@36.83,29.528 37.589,28.769 v1(37.745,28.769)
IMCU_SWDIO: J4.2 TP13.1 U3.AA31 | length 10.8
  Top Layer w0.125: U3.AA31@28.125,27.458 28.538,27.458 29.147,26.849 35.515,26.849 J4.2@36.135,26.229 v1(36.945,26.229)
  Bottom Layer w0.125: v1(36.945,26.229) 36.945,24.777 TP13.1@36.957,24.765
"IN 3-4_S4": R32.2 U7_S4.10 | length 2.8
  Top Layer w0.125: U7_S4.10@30.1,38.874 30.1,39.399 30.2,39.499 31.535,39.499 R32.2@32.1,38.934
INT_EXT: R50.1 U5.11 U8_S7.11 | length 4.8
  Top Layer w0.15: U8_S7.11@98.428,32.149 98.799,31.779 v2(99.215,31.779) ; v2(101.118,32.197) 101.47,32.548 ; 101.47,32.549 101.91,32.549 102.31,32.149 U5.11@102.585,32.149
  Mid-Layer 1 w0.15: v2(99.215,31.779) 100.7,31.779 v2(101.118,32.197)
IOEXP_CTRL: R47.2 U3.A17 U7_S5.2 U7_S5.10 U7_S6.2 U7_S6.10 U8_S7.2 | length 102.2
  Top Layer w0.125: U3.A17@25.125,31.658 25.125,31.685 25.175,31.735 25.175,33.933 27.216,35.974 43.5,35.974 v1(43.975,35.499)
  Top Layer w0.152: v2(97.5,32.274) 97.5,30.644 99.28,28.864 99.28,28.76 v2(99.308,28.732) ; v2(98.875,32.249) 98.975,32.149 U8_S7.2@99.825,32.149 ; v2(100.475,33.149) 100.475,35.249 v1(100.225,35.499) 100.785,36.059 R47.2@100.825,36.059 100.875,36.109 v2(100.875,36.549) ; v2(101.966,27.683) U7_S6.10@102.585,27.683 102.997,27.683 103.505,27.175 103.872,27.175 103.979,27.283 U7_S6.2@104.235,27.283 ; v2(102.05,36.549) 102.191,36.408 U7_S5.2@102.585,36.408 102.84,36.408 103.147,36.1 103.517,36.1 103.61,36.008 U7_S5.10@104.235,36.008
  Mid-Layer 1 w0.152: v2(97.5,32.274) v2@98.85,32.274 ; v2@98.864,32.238 v2(98.875,32.249) v2@98.85,32.274 ; v2(99.308,28.732) 100.357,27.683 v2(101.966,27.683) ; v2(100.475,33.149) 99.053,33.149 98.799,32.894 98.799,32.325 v2@98.85,32.274 ; v2(100.875,36.549) v2(102.05,36.549)
  Bottom Layer w0.125: v1(43.975,35.499) 44.233,35.757 59.391,35.757 60.575,34.574 69.225,34.574 70.408,35.757 86.423,35.757 86.819,35.361 87.262,35.361 87.908,36.007 99.716,36.007 v1(100.225,35.499)
LED1: Q4.2 R43.2 U7_S5.16 | length 28
  Top Layer w0.15: U7_S5.16@102.81,37.433 102.81,39.092 104.81,41.092 104.81,51.928 102.72,54.017 102.72,55.706 103.714,56.699 106.25,56.699 107.149,57.598 107.149,59.656 107.392,59.899 107.65,59.899 Q4.2@107.75,59.999
LED1_EXT: U5.7 U7_S5.15 | length 4.4
  Top Layer w0.15: U5.7@103.21,33.574 v2(103.21,34.085) ; U7_S5.15@103.21,37.433 103.21,37.124 103.535,36.799 v2(103.61,36.799)
  Mid-Layer 1 w0.15: v2(103.21,34.085) 103.76,34.635 103.76,36.649 v2(103.61,36.799)
LED2: Q4.5 R44.2 U7_S5.4 | length 31.9
  Top Layer w0.15: U7_S5.4@102.585,35.608 101.931,35.608 101.685,35.854 101.685,38.745 104.26,41.32 104.26,46.906 103.9,47.266 103.9,48.999 104.475,49.574 104.475,51.874 102.125,54.224 102.125,56.013 103.311,57.199 106.361,57.199 106.851,57.689 106.851,59.802 106.655,59.999 106.25,59.999 Q4.5@106.349,59.9
LED2_EXT: U5.8 U7_S5.3 | length 3.3
  Top Layer w0.15: v2(102.035,35.999) 102.044,36.008 U7_S5.3@102.585,36.008 ; v2(102.635,34.049) 102.81,33.874 U5.8@102.81,33.574
  Mid-Layer 1 w0.15: v2(102.035,35.999) 102.035,34.649 v2(102.635,34.049)
LED3: Q5.2 R45.2 U7_S5.8 | length 22.1
  Top Layer w0.15: U7_S5.8@104.01,34.983 104.459,34.983 106.704,37.228 106.704,44.82 106.402,45.122 106.402,51.801 107.149,52.548 107.149,54.552 107.345,54.749 Q5.2@107.75,54.749
LED3_EXT: U5.9 U7_S5.7 | length 3.3
  Top Layer w0.15: U5.9@102.585,32.949 102.201,33.332 102.201,34.191 102.469,34.458 103.344,34.458 103.61,34.724 U7_S5.7@103.61,34.983
LED4: Q5.5 R46.2 U7_S5.12 | length 20.2
  Top Layer w0.15: U7_S5.12@104.235,36.808 104.684,36.808 106.154,38.278 106.154,43.911 105.802,44.263 105.802,44.327 105.801,44.328 105.801,44.8 106.125,45.124 106.125,51.916 106.851,52.643 106.851,54.552 106.655,54.749 106.25,54.749 Q5.5@106.349,54.65
LED4_EXT: U5.10 U7_S5.11 | length 5.9
  Top Layer w0.15: v2(102.41,34.924) 101.91,34.424 101.91,32.971 102.331,32.549 U5.10@102.585,32.549 ; v2(103.26,36.499) 103.351,36.408 U7_S5.11@104.235,36.408
  Mid-Layer 1 w0.15: v2(102.41,34.924) 102.41,35.649 v2(103.26,36.499)
LTE_RF1: J1.1 M1.35 | length 14.7
  Top Layer w1: 125.85,19.552 ccw(c126.703,19.552) 126.1,18.949 ccw(c127.066,19.915) 127.066,18.549 J1.1@140.05,18.549
MAGPIO0: M1.21 P24.9 P27.9 | length 42.8
  Top Layer w0.15: v1(93.027,43.18) 94.294,43.18 95.25,42.224 95.25,39.849 96.364,38.735 96.369,38.735 96.505,38.599 v1(96.6,38.599) ; v1(118.387,19.749) 118.442,19.804 118.705,19.804 118.884,19.983 118.884,20.34 M1.21@118.85,20.374
  Bottom Layer w0.15: v1(96.6,38.599) 99.339,38.599 99.589,38.349 102.539,38.349 103.205,39.016 107.089,39.016 111.53,34.574 111.536,34.574 111.8,34.31 111.8,34.304 118.562,27.542 118.562,20.019 118.387,19.844 v1(118.387,19.749)
MAGPIO1: M1.22 P24.10 P27.10 | length 39.9
  Top Layer w0.15: v1(97.472,43.18) 98.744,43.18 99.775,42.149 v1(99.775,38.799) ; v1(118.883,19.316) 119.35,19.784 M1.22@119.35,20.374
  Bottom Layer w0.15: v1(99.775,38.799) 102.6,38.799 103.091,39.291 107.497,39.291 118.883,27.905 v1(118.883,19.316)
MAGPIO2: M1.23 P24.11 P27.11 | length 42
  Top Layer w0.15: v1(119.444,19.041) 119.85,19.447 M1.23@119.85,20.374
  Bottom Layer w0.15: P27.11@93.027,40.64 94.297,40.64 95.388,39.549 101.492,39.549 101.508,39.566 107.611,39.566 119.275,27.902 119.275,21.585 119.444,21.416 v1(119.444,19.041)
  other v1: 94,40.749
MIPI_SCLK: M1.28 P24.6 P27.6 | length 44.2
  Top Layer w0.15: v1(97.472,48.26) 98.739,48.26 100.96,46.039 100.96,40.751 100.789,40.58 v1(100.789,40.488) ; v1(121.6,21.477) 121.6,21.464 121.929,21.135 122.275,20.789 122.275,20.449 M1.28@122.35,20.374
  Bottom Layer w0.15: v1(100.789,40.488) 100.803,40.474 107.481,40.474 119.85,28.105 119.85,21.788 120.614,21.024 121.147,21.024 v1(121.6,21.477)
MIPI_SDATA: M1.27 P24.5 P27.5 | length 47.2
  Top Layer w0.15: v1(93.027,48.26) 94.289,48.26 95.55,46.999 99.611,46.999 100.5,46.11 v1(100.5,41.049) ; v1(120.8,21.474) 120.848,21.426 120.848,21.151 121.2,20.799 121.687,20.799 121.775,20.711 121.775,20.449 M1.27@121.85,20.374
  Bottom Layer w0.15: v1(100.5,41.049) 102.464,41.049 102.764,40.749 107.595,40.749 120.125,28.219 120.125,22.149 v1(120.8,21.474)
MIPI_VIO: M1.29 P24.7 P27.7 | length 47
  Top Layer w0.15: v1(93.027,45.72) 94.304,45.72 95.575,44.449 99.45,44.449 100.05,43.849 100.05,40.385 100.4,40.035 v1(100.4,39.999) ; v1(122.3,21.499) 122.367,21.432 122.367,21.099 122.775,20.691 122.775,20.449 M1.29@122.85,20.374
  Bottom Layer w0.15: v1(100.4,39.999) 107.567,39.999 119.55,28.016 119.55,21.699 120.5,20.749 121.55,20.749 v1(122.3,21.499)
NC.CH1_S3: R22.2 U7_S3.1 | length 1.4
  Top Layer w0.15: U7_S3.1@17.425,26.849 18.624,26.849 R22.2@18.79,26.683
NC.CH1_S4: U7_S4.1
NC.CH1_S7: U8_S7.1
NC.CH1_S9: C49.2 U6.8 U8_S9.1 | length 11.7
  Top Layer w0.2: U6.8@78.75,16.154 79.955,16.154 84.5,20.699 85.915,20.699 87.146,19.468 87.146,18.778 U8_S9.1@87.275,18.649
NC.CH2_S4: U7_S4.5
NC.CH2_S7: U8_S7.5
NC.CH2_S9: U6.6 U8_S9.5 | length 11.1
  Top Layer w0.2: U6.6@78.75,13.614 79.05,13.614 79.675,14.239 79.675,14.574 82.675,17.574 v2(83.15,17.574) ; v2(87.175,16.999) 87.325,16.999 U8_S9.5@87.5,16.824 U8_S9.5@87.5,17.049
  Mid-Layer 1 w0.2: v2(83.15,17.574) 83.425,17.299 86.875,17.299 v2(87.175,16.999)
NC.CH2_S10: SB21.1 U7_S10.5 | length 1.6
  Top Layer w0.15: SB21.1@57.5,20.587 SB21.1@57.5,20.599 57.5,21.624 U7_S10.5@57.9,22.024
NC.CH3_S3: R20.2 U7_S3.9 | length 4.8
  Top Layer w0.125: U7_S3.9@15.775,28.049 15.55,28.049 15.3,28.299 15.3,29.043 15.515,29.258 R20.2@18.69,29.258
NC.CH3_S4: U7_S4.9
NC.CH3_S7: U8_S7.9
NC.CH3_S9: SB13.2 SB14.2 U8_S9.9 | length 24.5
  Top Layer w0.2: SB14.2@71.162,13.249 71.162,16.911 72.5,18.249 80.8,18.249 v1(81.55,18.999) ; U8_S9.9@88.925,17.449 v1(89.65,17.449)
  Bottom Layer w0.2: v1(81.55,18.999) 82,18.549 86.25,18.549 87.55,17.249 89.45,17.249 v1(89.65,17.449)
NC.CH4_S3: R19.2 U7_S3.13 | length 7.5
  Top Layer w0.125: U7_S3.13@16,26.224 15.625,26.224 15.05,26.799 15.05,29.146 15.412,29.508 18.34,29.508 R19.2@18.69,29.858
NC.CH4_S4: U7_S4.13
NC.CH4_S7: U8_S7.13
NC.CH4_S9: U6.7 U8_S9.13 | length 13
  Top Layer w0.2: U6.7@78.75,14.884 79.285,14.884 84.725,20.324 v2(85.4,20.324) ; U8_S9.13@88.7,19.274 v2(88.7,19.849)
  Mid-Layer 1 w0.2: v2(85.4,20.324) 85.415,20.309 88.24,20.309 v2(88.7,19.849)
NC.CH4_S10: U7_S10.13
NC.CH4_S11: U7_S11.13
NetC7_1: C7.1 FB1.2 M1.14 R1.1 | length 4.5
  Top Layer w0.3: C7.1@115.675,25.599 115.875,25.799 R1.1@116.315,25.799 116.175,25.659 116.175,24.024 116.4,23.799 FB1.2@116.875,23.799 116.925,23.749 M1.14@117.975,23.749
NetC8_2: C8.2 C9.2 C50.2 FB2.1 J6.A4 J6.A9 TP17.1 U1.1 | length 12.5
  Top Layer w0.45: J6.A9@8.985,29.299 8.489,29.299 ccw(c7.915,28.809) 7.896,29.564 7.535,29.564 cw(c7.535,30.099) 7,30.099 v1(7,31.999) v1(7,32.499) v1(7,32.999) 7,33.199 cw(c7.635,33.199) 7.635,33.834 7.896,33.834 ccw(c7.915,34.589) 8.489,34.099 J6.A4@8.985,34.099
  Bottom Layer w0.45: TP17.1@6.248,36.323 6.3,36.271 6.3,33.999 7,33.299 v1(7,32.999) v1(7,32.499) v1(7,31.999)
NetC10_1: C10.1 M1.9 R2.2 | length 2.9
  Top Layer w0.15: R2.2@115.125,26.474 115.14,26.474 R2.2@115.2,26.414 C10.1@115.8,26.414 ; C10.1@115.875,26.339 116.015,26.199 116.411,26.199 116.434,26.176 116.83,26.176 116.903,26.249 M1.9@117.975,26.249
NetC19_2: C19.2 L4.2 | length 0.8
  Top Layer w0.203: C19.2@133.315,30.879 L4.2@134.155,30.879
NetC36_2: C36.2 U3.A15 | length 2.7
  Top Layer w0.225: C36.2@24.675,34.263 24.875,34.063 24.875,32.008 24.725,31.858 U3.A15@24.725,31.658
NetC37_1: C37.1 R21.2 U3.A5 | length 5.3
  Top Layer w0.15: U3.A5@22.725,31.658 U3.A5@22.75,31.683
  Top Layer w0.18: U3.A5@22.745,31.683 22.745,31.773
  Top Layer w0.2: R21.2@18.625,33.564 19.794,33.564 20.434,32.923 22.026,32.923 22.725,32.224 U3.A5@22.725,31.658
NetC44_1: C44.1 D1.3 R53.1 U5.2 | length 3.6
  Top Layer w0.15: U5.2@104.235,32.149 104.516,32.149 104.78,31.886 104.78,30.961 105.174,30.567 C44.1@105.174,30.475 D1.3@105.784,30.475 ; D1.3@105.789,30.317 105.789,29.62 R53.1@105.829,29.58
NetC45_2: C45.2 D2.3 R55.1 U5.3 | length 2.6
  Top Layer w0.15: U5.3@104.235,32.549 104.581,32.549 C45.2@105.182,31.948 ; C45.2@105.174,31.948 C45.2@105.182,31.948 ; D2.3@105.784,31.948 C45.2@105.182,31.948 ; D2.3@105.789,31.79 105.789,31.094 R55.1@105.829,31.054
NetC46_2: C46.2 D3.3 R57.1 U5.4 | length 2.5
  Top Layer w0.15: U5.4@104.235,32.949 104.67,32.949 105.142,33.421 C46.2@105.174,33.421 D3.3@105.784,33.421 ; D3.3@105.789,33.263 105.789,32.567 R57.1@105.829,32.527
NetC47_2: C47.2 D4.3 R61.1 U5.5 | length 3.5
  Top Layer w0.15: U5.5@104.01,33.574 104.34,33.574 104.771,34.005 104.771,34.668 104.997,34.895 C47.2@105.174,34.895 D4.3@105.784,34.895 ; D4.3@105.789,34.737 105.789,34.04 R61.1@105.829,34
NetC57_2: C57.2 C67.2 FB4.1 U9.20 | length 0.9
  Top Layer w0.3: C67.2@6.327,14.796 7.027,14.796 ccw(c7.027,14.896) C57.2@7.127,14.896
NetC59_2: C59.2 C71.2 FB6.1 L8.1 U9.32 | length 12
  Top Layer w0.2: v1(14.234,10.923) 14.275,10.964 U9.32@14.275,11.724
  Bottom Layer w0.2: v1(14.234,10.923) 18.324,10.923 19.8,12.399 v1(19.8,17.399)
NetC61_1: C61.1 C63.1 J6.SHLD | length 2.7
  Top Layer w0.3: C63.1@8.2,26.099 8.2,27.184 J6.SHLD@8.395,27.379 ; J6.SHLD@8.395,36.029 8.4,36.034 C61.1@8.4,37.399
NetC70_2: C70.2 FB5.2 SB33.1
NetD5_1: D5.1 J5.C2 | length 1.7
  Top Layer w0.2: v2(84.45,16.824) D5.1@84.45,17.324
  Mid-Layer 1 w0.2: v2(84.45,16.824) 84.45,15.924 v2(84.65,15.724)
NetD5_2: D5.2 J5.C3 | length 3.9
  Top Layer w0.2: J5.C3@82.3,15.299 82.3,15.524 82.9,16.124 83.69,16.124 84.015,16.449 84.619,16.449 84.95,16.78 D5.2@84.95,17.324
NetD5_3: D5.3 J5.C7 | length 3.2
  Top Layer w0.2: J5.C7@83.57,15.299 83.57,15.544 84.15,16.124 84.753,16.124 85.45,16.821 D5.3@85.45,17.324
NetJ5_CD: J5.CD R62.2 R63.2 | length 7.4
  Top Layer w0.15: J5.CD@89.6,15.299 v1(90.525,15.299) ; R63.2@92.085,19.699 R62.2@92.665,19.699 92.665,18.559 93.175,18.049 v1(93.275,18.049)
  Bottom Layer w0.15: v1(90.525,15.299) v1(93.275,18.049)
NetJ6_A5: J6.A5 R71.2 | length 1.5
  Top Layer w0.125: J6.A5@8.985,32.954 8.999,32.968 9.669,32.968 9.8,33.099 9.8,33.367 9.873,33.441 10.057,33.441 R71.2@10.115,33.499
NetJ6_B5: J6.B5 R70.2 | length 1.1
  Top Layer w0.125: J6.B5@8.985,29.954 10.07,29.954 R70.2@10.115,29.999
NetLED1_1: LED1.1 Q4.6 | length 4.1
  Top Layer w0.254: LED1.1@103.301,59.999 103.301,59.24 103.827,58.715 105.304,58.715 Q4.6@106.039,59.451 ; Q4.6@106.202,59.451 Q4.6@106.25,59.499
